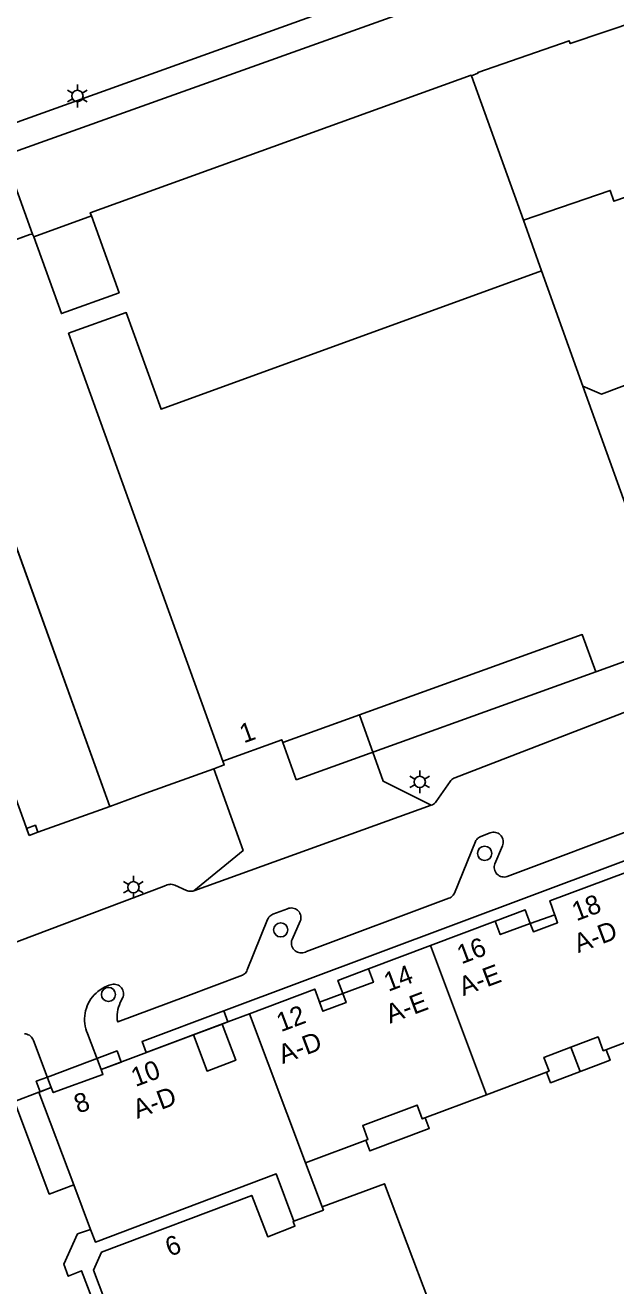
# Model space of a CAD drawing. Extents: x 122462 to 123306, y 485548 to 486417.
# Drawn here: x 122519.5 to 122566.2, y 485673.5 to 485773.2 of the extents above; entities that cross this region are included whole.
import ezdxf

# ---------------------------------------------------------------- set-up
doc = ezdxf.new("R2010")
doc.units = 0
for name, color, linetype in [('Level 1', 7, 'Continuous'), ('Level 10', 7, 'Continuous'), ('Level 11', 7, 'Continuous'), ('Level 17', 7, 'Continuous'), ('Level 19', 7, 'Continuous'), ('Level 22', 7, 'Continuous'), ('Level 34', 7, 'Continuous'), ('Level 4', 7, 'Continuous'), ('Level 5', 7, 'Continuous'), ('Level 50', 7, 'Continuous'), ('Level 53', 7, 'Continuous'), ('Level 58', 7, 'Continuous')]:
    doc.layers.add(name, color=color, linetype=linetype)

msp = doc.modelspace()

# ---------------------------------------------------------------- linework, layer by layer
at = {"layer": 'Level 1'}
for p, q in [((122524.761, 485758.082), (122520.199, 485756.429)), ((122560.372, 485753.746), (122558.935, 485757.75)), ((122563.647, 485744.62), (122560.372, 485753.746)), ((122570.939, 485724.289), (122563.647, 485744.62)), ((122532.832, 485693.313), (122535.1, 485694.168)), ((122525.531, 485690.561), (122532.832, 485693.313)), ((122518.673, 485688.045), (122520.616, 485688.777)), ((122520.616, 485688.777), (122521.591, 485689.151)), ((122541.714, 485683.189), (122543.026, 485679.702))]:
    msp.add_line(p, q, dxfattribs=at)
for points in [[(122595.705, 485783.261), (122588.35, 485780.749), (122588.42, 485780.539), (122577.601, 485776.821), (122577.531, 485777.031), (122573.371, 485775.601), (122573.443, 485775.393), (122562.65, 485771.719), (122562.57, 485771.939), (122555.33, 485769.42), (122555.347, 485769.372), (122554.835, 485769.176)], [(122558.935, 485757.75), (122565.807, 485760.105), (122566.103, 485759.241), (122573.182, 485761.667), (122572.886, 485762.531), (122575.552, 485763.445), (122576.058, 485761.968), (122583.208, 485764.419), (122582.702, 485765.895), (122585.619, 485766.895), (122585.915, 485766.032), (122592.763, 485768.378), (122592.467, 485769.242), (122599.667, 485771.71)], [(122554.835, 485769.176), (122554.82, 485769.209), (122524.67, 485758.329), (122524.761, 485758.082)], [(122520.199, 485756.429), (122520.11, 485756.65), (122519.901, 485756.601), (122516.856, 485755.503), (122511.049, 485753.41), (122518.197, 485733.594), (122526.209, 485711.38), (122529.079, 485712.419), (122534.438, 485714.36)], [(122545.965, 485718.624), (122563.597, 485724.974), (122564.658, 485722.028), (122570.939, 485724.289)], [(122535.163, 485714.962), (122539.822, 485716.649), (122539.898, 485716.439), (122545.965, 485718.624)], [(122534.438, 485714.36), (122535.269, 485714.66), (122535.163, 485714.962)], [(122551.589, 485700.372), (122556.719, 485702.299), (122557.108, 485701.246), (122559.488, 485702.127), (122559.73, 485701.474), (122561.644, 485702.183), (122561.039, 485703.92), (122567.04, 485706.164)], [(122537.268, 485694.984), (122542.429, 485696.929), (122543.077, 485695.183), (122544.916, 485695.863), (122544.651, 485696.58), (122547.068, 485697.473), (122546.689, 485698.529), (122551.589, 485700.372)], [(122535.1, 485694.168), (122535.555, 485694.339), (122537.268, 485694.984)], [(122571.262, 485694.96), (122570.331, 485694.609), (122570.543, 485694.046), (122565.253, 485692.054), (122564.842, 485693.145), (122562.701, 485692.339)], [(122562.701, 485692.339), (122560.561, 485691.533), (122560.972, 485690.442), (122556.033, 485688.582)], [(122521.591, 485689.151), (122521.739, 485688.743), (122525.672, 485690.172), (122525.531, 485690.561)], [(122556.033, 485688.582), (122550.942, 485686.664), (122550.531, 485687.755), (122546.233, 485686.137), (122546.644, 485685.045), (122541.714, 485683.189)], [(122543.026, 485679.702), (122547.951, 485681.541), (122553.241, 485667.511), (122546.311, 485664.908), (122547.777, 485661.013)]]:
    msp.add_lwpolyline(points, dxfattribs=at)
at = {"layer": 'Level 10'}
for points in [[(122519.84, 485709.069), (122520.535, 485709.334), (122526.209, 485711.38), (122511.049, 485753.41), (122519.901, 485756.601), (122520.11, 485756.65), (122514.9, 485771.059), (122514.741, 485770.971), (122514.241, 485770.791), (122514.141, 485771.021), (122508.443, 485768.964), (122508.528, 485768.729), (122507.89, 485768.498), (122507.805, 485768.733), (122506.416, 485768.232), (122506.501, 485767.997), (122505.862, 485767.766), (122505.777, 485768.001), (122500.08, 485765.961), (122500.159, 485765.742), (122499.489, 485765.499), (122519.84, 485709.069)], [(122540.959, 485713.492), (122539.898, 485716.439), (122563.597, 485724.974), (122564.658, 485722.028), (122540.959, 485713.492)], [(122559.488, 485702.127), (122561.43, 485702.801), (122561.644, 485702.183), (122559.73, 485701.474), (122559.488, 485702.127)], [(122544.651, 485696.58), (122544.916, 485695.863), (122543.077, 485695.183), (122542.812, 485695.9), (122544.651, 485696.58)], [(122529.103, 485691.907), (122528.772, 485692.784), (122535.229, 485695.204), (122535.555, 485694.339), (122529.103, 485691.907)], [(122521.739, 485688.743), (122521.591, 485689.151), (122520.717, 485688.815), (122520.395, 485689.646), (122521.279, 485689.977), (122526.796, 485692.045), (122527.128, 485691.163), (122525.531, 485690.561), (122525.672, 485690.172), (122521.739, 485688.743)]]:
    msp.add_lwpolyline(points, dxfattribs=at)
at = {"layer": 'Level 11'}
for points in [[(122556.719, 485702.299), (122559.09, 485703.189), (122559.488, 485702.127)], [(122546.689, 485698.529), (122544.261, 485697.618), (122544.651, 485696.58)], [(122565.484, 485692.141), (122565.801, 485691.301), (122561.085, 485689.525), (122560.768, 485690.365)], [(122551.172, 485686.751), (122551.489, 485685.911), (122546.783, 485684.139), (122546.467, 485684.978)]]:
    msp.add_lwpolyline(points, dxfattribs=at)
at = {"layer": 'Level 17'}
msp.add_line((122551.651, 485711.476), (122532.876, 485704.714), dxfattribs=at)
for points in [[(122553.788, 485778.048), (122513.731, 485763.641)], [(122556.723, 485776.778), (122517.869, 485762.854)], [(122551.651, 485711.476), (122547.856, 485713.372), (122545.965, 485718.624)], [(122568.671, 485719.499), (122553.517, 485713.644), (122553.431, 485713.605), (122553.351, 485713.556), (122553.277, 485713.498), (122553.21, 485713.432), (122553.152, 485713.358), (122552.034, 485711.768), (122551.973, 485711.692), (122551.903, 485711.624), (122551.825, 485711.564), (122551.741, 485711.515), (122551.651, 485711.476)], [(122534.438, 485714.36), (122536.767, 485707.89), (122532.876, 485704.714)], [(122541.486, 485699.803), (122541.593, 485699.827), (122541.694, 485699.866), (122541.79, 485699.919), (122553.053, 485704.118), (122553.144, 485704.162), (122553.228, 485704.216), (122553.306, 485704.28), (122553.375, 485704.354), (122553.434, 485704.435), (122553.483, 485704.523), (122555.143, 485708.605), (122555.187, 485708.694), (122555.244, 485708.775), (122555.312, 485708.847), (122555.39, 485708.908), (122555.476, 485708.957), (122555.568, 485708.993), (122556.321, 485709.299), (122556.422, 485709.328), (122556.526, 485709.342), (122556.632, 485709.343), (122556.736, 485709.329), (122556.837, 485709.3), (122556.934, 485709.259), (122557.024, 485709.204), (122557.106, 485709.138), (122557.178, 485709.061), (122557.238, 485708.975), (122557.287, 485708.881), (122557.322, 485708.782), (122557.343, 485708.679), (122557.35, 485708.574), (122557.343, 485708.469), (122557.321, 485708.366), (122557.286, 485708.267), (122556.68, 485706.842), (122556.649, 485706.737), (122556.633, 485706.629), (122556.633, 485706.52), (122556.648, 485706.412), (122556.678, 485706.307), (122556.722, 485706.207), (122556.78, 485706.114), (122556.85, 485706.031), (122556.932, 485705.958), (122557.022, 485705.897), (122557.121, 485705.85), (122557.225, 485705.817), (122557.333, 485705.799), (122557.442, 485705.796), (122557.55, 485705.808), (122557.656, 485705.836), (122568.344, 485709.854)], [(122532.876, 485704.714), (122532.777, 485704.685), (122532.676, 485704.669), (122532.573, 485704.666), (122532.47, 485704.677), (122532.37, 485704.701), (122532.274, 485704.737), (122531.363, 485705.15), (122531.265, 485705.187), (122531.164, 485705.211), (122531.06, 485705.221), (122530.956, 485705.218), (122530.853, 485705.201), (122530.753, 485705.171), (122530.52, 485705.083), (122508.8, 485696.87)], [(122525.531, 485690.561), (122524.456, 485693.415), (122524.382, 485693.606), (122524.321, 485693.802), (122524.275, 485694.002), (122524.244, 485694.204), (122524.227, 485694.409), (122524.225, 485694.614), (122524.238, 485694.818), (122524.266, 485695.021), (122524.308, 485695.222), (122524.364, 485695.419), (122524.435, 485695.612), (122524.519, 485695.798), (122524.617, 485695.979), (122524.727, 485696.151), (122524.85, 485696.316), (122524.984, 485696.471), (122525.129, 485696.616), (122525.284, 485696.75), (122525.449, 485696.872), (122525.621, 485696.983), (122525.802, 485697.08), (122525.988, 485697.165), (122526.181, 485697.235), (122526.378, 485697.292), (122526.483, 485697.31), (122526.589, 485697.313), (122526.695, 485697.302), (122526.798, 485697.275), (122526.896, 485697.234), (122526.988, 485697.179), (122527.07, 485697.112), (122527.143, 485697.034), (122527.203, 485696.947), (122527.251, 485696.852), (122527.285, 485696.751), (122527.304, 485696.646), (122527.308, 485696.54), (122527.297, 485696.434), (122527.271, 485696.331), (122527.231, 485696.232), (122527.134, 485696.057), (122527.049, 485695.877), (122526.976, 485695.691), (122526.915, 485695.501), (122526.866, 485695.307), (122526.83, 485695.11), (122526.807, 485694.912), (122526.797, 485694.713), (122526.799, 485694.513), (122526.865, 485694.338), (122532.236, 485696.349), (122536.722, 485698.029), (122536.806, 485698.075), (122536.883, 485698.133), (122536.95, 485698.201), (122537.008, 485698.278), (122537.054, 485698.362), (122537.087, 485698.452), (122538.706, 485702.432), (122538.749, 485702.524), (122538.805, 485702.61), (122538.872, 485702.688), (122538.948, 485702.755), (122539.033, 485702.812), (122539.125, 485702.857), (122540.289, 485703.289), (122540.388, 485703.323), (122540.49, 485703.343), (122540.595, 485703.349), (122540.699, 485703.34), (122540.801, 485703.317), (122540.899, 485703.28), (122540.991, 485703.23), (122541.075, 485703.168), (122541.15, 485703.095), (122541.214, 485703.012), (122541.265, 485702.922), (122541.304, 485702.825), (122541.329, 485702.723), (122541.34, 485702.619), (122541.337, 485702.515), (122541.319, 485702.412), (122541.287, 485702.312), (122540.639, 485700.859), (122540.606, 485700.755), (122540.589, 485700.647), (122540.586, 485700.538), (122540.599, 485700.43), (122540.627, 485700.324), (122540.669, 485700.224), (122540.724, 485700.13), (122540.793, 485700.045), (122540.872, 485699.97), (122540.961, 485699.907), (122541.058, 485699.857), (122541.161, 485699.821), (122541.268, 485699.8), (122541.377, 485699.794), (122541.486, 485699.803)], [(122521.591, 485689.151), (122520.182, 485692.879), (122520.139, 485692.974), (122520.084, 485693.063), (122520.017, 485693.144), (122519.941, 485693.215), (122519.856, 485693.276), (122519.764, 485693.326), (122519.667, 485693.363), (122519.565, 485693.387), (122519.461, 485693.398)]]:
    msp.add_lwpolyline(points, dxfattribs=at)
at = {"layer": 'Level 19'}
msp.add_lwpolyline([(122568.113, 485745.115), (122565.115, 485743.997), (122563.647, 485744.62)], dxfattribs=at)
at = {"layer": 'Level 22'}
msp.add_line((122562.701, 485692.339), (122563.43, 485690.408), dxfattribs=at)
msp.add_lwpolyline([(122535.229, 485695.204), (122577.981, 485711.222), (122578.295, 485710.39)], dxfattribs=at)
at = {"layer": 'Level 34'}
msp.add_lwpolyline([(122519.84, 485709.069), (122519.633, 485709.646), (122520.332, 485709.898), (122520.535, 485709.334), (122519.84, 485709.069)], dxfattribs=at)
at = {"layer": 'Level 4'}
for p, q in [((122558.935, 485757.75), (122554.835, 485769.176)), ((122556.033, 485688.582), (122551.589, 485700.372)), ((122520.616, 485688.777), (122523.372, 485681.458)), ((122523.372, 485681.458), (122524.704, 485677.919))]:
    msp.add_line(p, q, dxfattribs=at)
for points in [[(122543.026, 485679.702), (122543.121, 485679.451), (122540.79, 485678.573), (122539.383, 485682.311), (122525.079, 485676.924), (122524.704, 485677.919)], [(122524.809, 485672.502), (122523.991, 485674.651), (122522.931, 485674.221), (122522.571, 485675.171), (122523.671, 485677.571), (122524.704, 485677.919)]]:
    msp.add_lwpolyline(points, dxfattribs=at)
at = {"layer": 'Level 5'}
for p, q in [((122537.268, 485694.985), (122537.268, 485694.984)), ((122537.268, 485694.984), (122541.714, 485683.189))]:
    msp.add_line(p, q, dxfattribs=at)
for points in [[(122520.199, 485756.429), (122522.389, 485750.362), (122526.953, 485752.009), (122524.761, 485758.082)], [(122560.372, 485753.746), (122530.278, 485742.793), (122527.517, 485750.444), (122522.954, 485748.798), (122535.163, 485714.962)], [(122532.832, 485693.313), (122533.914, 485690.444), (122536.182, 485691.299), (122535.1, 485694.168)], [(122518.673, 485688.045), (122521.429, 485680.726), (122523.372, 485681.458)], [(122540.79, 485678.573), (122540.72, 485678.547), (122540.861, 485678.171), (122538.711, 485677.351), (122537.451, 485680.611), (122525.551, 485676.121), (122524.931, 485674.691), (122531.891, 485656.271), (122533.261, 485655.591), (122547.777, 485661.013)]]:
    msp.add_lwpolyline(points, dxfattribs=at)
at = {"layer": 'Level 50'}
for p, q in [((122523.656, 485768.018), (122523.656, 485768.468)), ((122523.266, 485767.793), (122522.876, 485768.018)), ((122524.435, 485768.018), (122524.045, 485767.793)), ((122523.266, 485767.343), (122522.876, 485767.118)), ((122523.656, 485766.668), (122523.656, 485767.118)), ((122524.435, 485767.118), (122524.045, 485767.343)), ((122550.349, 485713.541), (122549.959, 485713.766)), ((122550.739, 485713.766), (122550.739, 485714.216)), ((122551.518, 485713.766), (122551.128, 485713.541)), ((122550.349, 485713.091), (122549.959, 485712.866)), ((122550.739, 485712.416), (122550.739, 485712.866)), ((122551.518, 485712.866), (122551.128, 485713.091)), ((122528.088, 485705.436), (122528.088, 485705.886)), ((122527.698, 485705.211), (122527.308, 485705.436)), ((122527.698, 485704.761), (122527.308, 485704.536)), ((122528.867, 485705.436), (122528.477, 485705.211)), ((122528.867, 485704.536), (122528.477, 485704.761)), ((122528.088, 485704.086), (122528.088, 485704.536))]:
    msp.add_line(p, q, dxfattribs=at)
for centre in [(122523.656, 485767.568), (122550.739, 485713.316), (122528.088, 485704.986)]:
    msp.add_circle(centre, 0.45, dxfattribs=at)
at = {"layer": 'Level 53'}
for centre in [(122555.875, 485707.67), (122539.74, 485701.615), (122526.114, 485696.508)]:
    msp.add_circle(centre, 0.56, dxfattribs=at)

# ---------------------------------------------------------------- texts
at = {"layer": 'Level 58'}
for s, rotation, p in [('1', 19.93758, (122536.821, 485716.361)), ('18', 20.59886, (122563.132, 485702.29)), ('A-D', 20.59886, (122563.274, 485699.771)), ('16', 20.59886, (122554.037, 485698.888)), ('14', 20.59886, (122548.254, 485696.714)), ('A-E', 20.59886, (122554.179, 485696.368)), ('A-E', 20.59886, (122548.395, 485694.194)), ('12', 20.59886, (122539.759, 485693.521)), ('A-D', 20.59886, (122539.902, 485691.002)), ('10', 20.59886, (122528.256, 485689.182)), ('8', 19.9468, (122523.724, 485687.071)), ('A-D', 20.59886, (122528.399, 485686.663)), ('6', 20.69047, (122530.958, 485675.757))]:
    msp.add_text(s, height=1.5, rotation=rotation, dxfattribs=at).set_placement(p)

doc.saveas('drawing.dxf')
